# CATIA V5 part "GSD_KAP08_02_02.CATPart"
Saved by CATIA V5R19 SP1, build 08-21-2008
Part number: GSD_ANALYSIS_02
Description: Beispielmodell für Verbindungsüberprüfungsanalyse / Flächen.  Maik Hertha IT Consultants
Bounding box of the stored display mesh (mm): x 45.005 to 391.048, y -251.452 to 318.537, z 79.732 to 163.217
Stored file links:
  \GSD_BUCH_UEBUNG\GSD_KAP08_02_02.CATPart
  C:\Program Files\Dassault Systemes\B19\win_b64\startup\materials\Catalog.CATMaterial
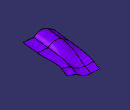
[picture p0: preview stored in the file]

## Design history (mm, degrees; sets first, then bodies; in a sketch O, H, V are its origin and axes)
AxisSystem1 "Absolute Axis System": origin (0, 0, 0), X (1, 0, 0), Y (0, 1, 0), Z (0, 0, 1)
Set1
  Sketch1 on XY plane of AxisSystem1, origin (0, 0, 0), H (1, 0, 0), V (0, 1, 0)
    spline S1 through (56.4923, -100.7832) (88.7426, 61.2206) (149.0894, 199.066)
  Sketch2 on YZ plane of AxisSystem1, origin (0, 0, 0), H (0, 1, 0), V (0, 0, 1)
    spline S1 through (-99.4141, 130.7483) (48.3525, 138.1953) (199.5081, 170.3531)
  Combine1: Curve1 Sketch2, Curve2 Sketch1
Set2
  Set3
    Plane1: type Normal, Curve Combine1, RefPoint {point type OnCurve, Support Combine1, Ratio 0}
    Sketch3 on Plane1, origin (149.0894, 199.066, 170.2213), H (0.8711, -0.4912, 0), V (-0.1233, -0.2188, 0.968)
      point P1 (0, -41.2234)
      line L1 (0, -41.2234) -> (55.1042, -60.3398)
      arc A1 centre (87.2142, 32.2196) radius 97.9708 from (55.1042, -60.3398) to (140.0568, -50.2785) ccw
      line L2 (140.0568, -50.2785) -> (199.1543, -50.2785)
      axis line L3 (0, -25.1255) -> (0, -95.554)
      point P6 (0, -25.1255)
      coincidence: P1 V, P6 V, P1 L3
      tangency: A1 L1
      horizontal: L2 H
      vertical: L3 V
    Extrude1: Lim1 131, Lim2 0, Element1 Sketch3, Direction Plane1
  Set4
    Plane2: type Normal, Curve Combine1, RefPoint {point type OnCurve, Support Combine1, Ratio 1}
    Sketch4 on Plane2, origin (56.6116, -99.4141, 130.7483), H (0.9961, -0.0877, 0), V (0.0023, 0.0264, 0.9996)
      point P1 (0, -50.7831)
      line L1 (0, -50.7831) -> (48.6659, -18.7973)
      arc A1 centre (92.7068, -85.8047) radius 80.1848 from (48.6659, -18.7973) to (154.6959, -34.9426) cw
      line L2 (154.6959, -34.9426) -> (235.5792, -34.9426)
      axis line L3 (0, -29.7328) -> (0, -112.44)
      point P6 (0, -29.7328)
      tangency: A1 L1
      horizontal: L2 H
      coincidence: P6 V, P1 L3
      vertical: L3 V
    Extrude2: Lim1 131, Lim2 0, Element1 Sketch4, Direction Plane2
  Loft1: Spine Combine1, Sections (Sketch4; Sketch3), EndSectionTangent Extrude1, StartSectionTangent Extrude2
Set5
  Join1: Elements (Extrude1; Loft1; Extrude2)
Body1 (main body)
